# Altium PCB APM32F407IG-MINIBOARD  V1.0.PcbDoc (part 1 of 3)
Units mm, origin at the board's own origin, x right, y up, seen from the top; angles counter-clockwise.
Board outline 442.79 x 366.46 mm, 2 copper layers (Top Layer, Bottom Layer); 220 components, 190 nets, 1232 pads, 648 vias.
Unrouted connection lines stored in the file: 190.
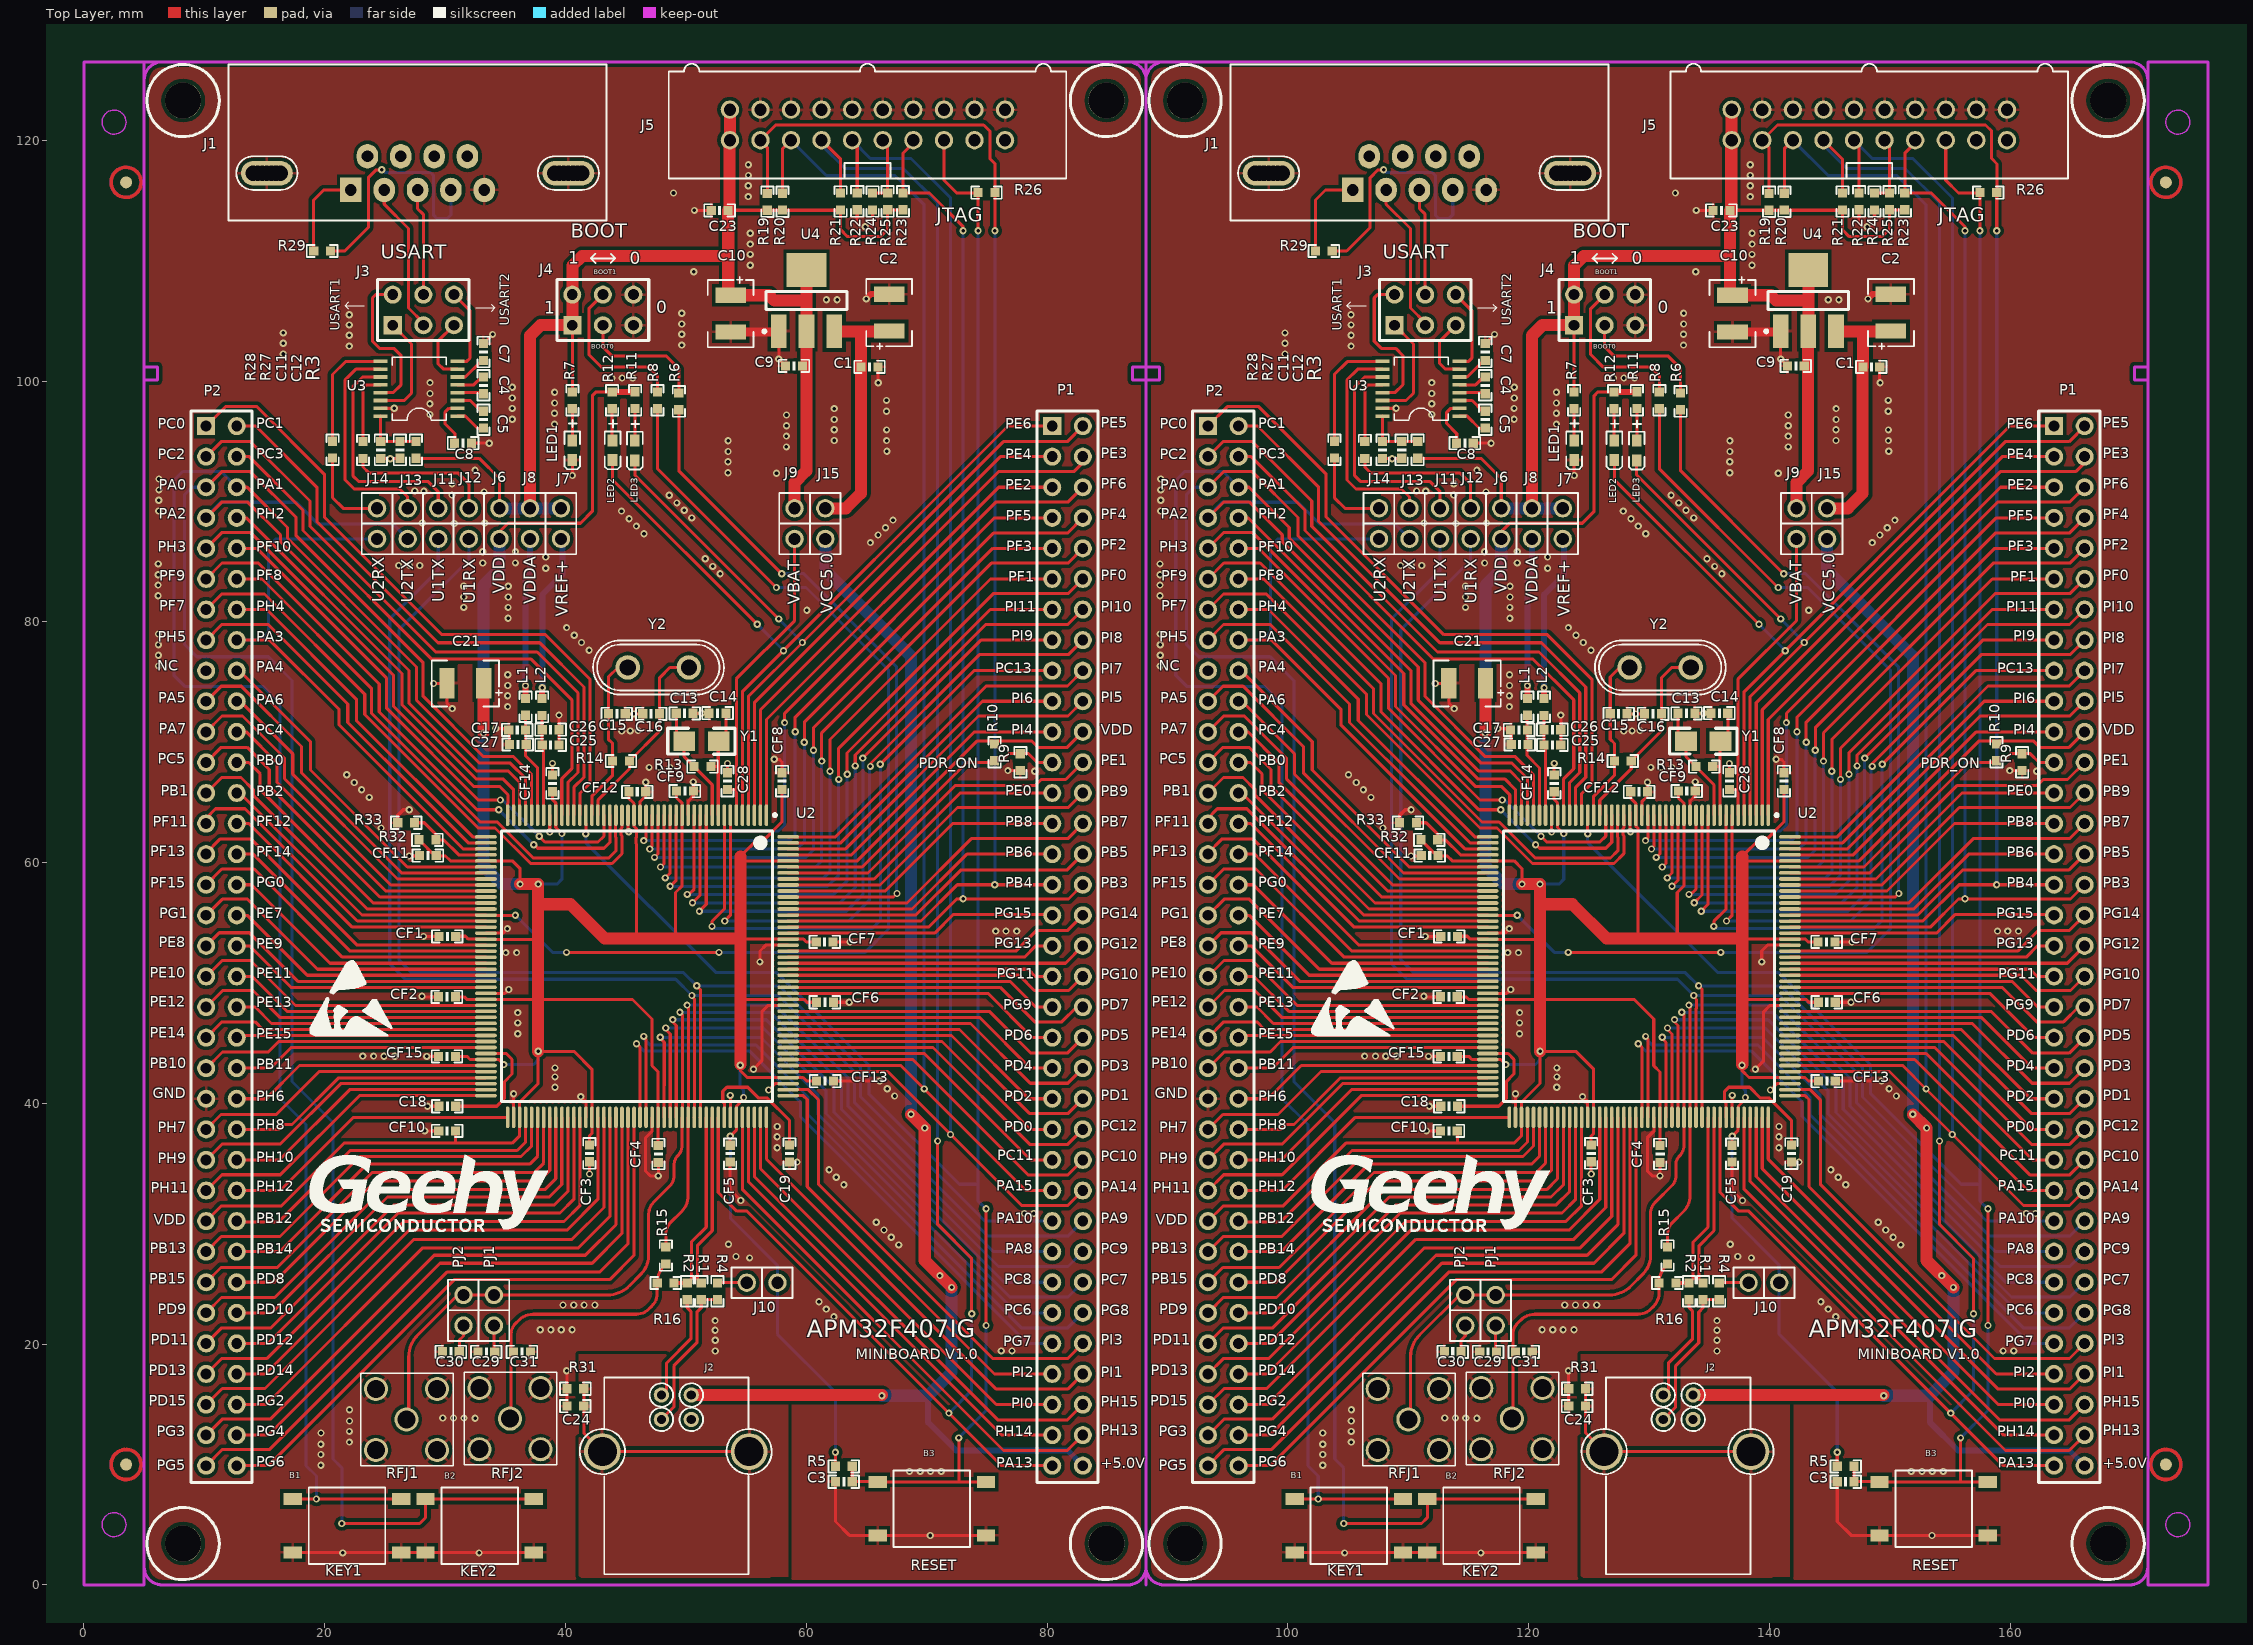
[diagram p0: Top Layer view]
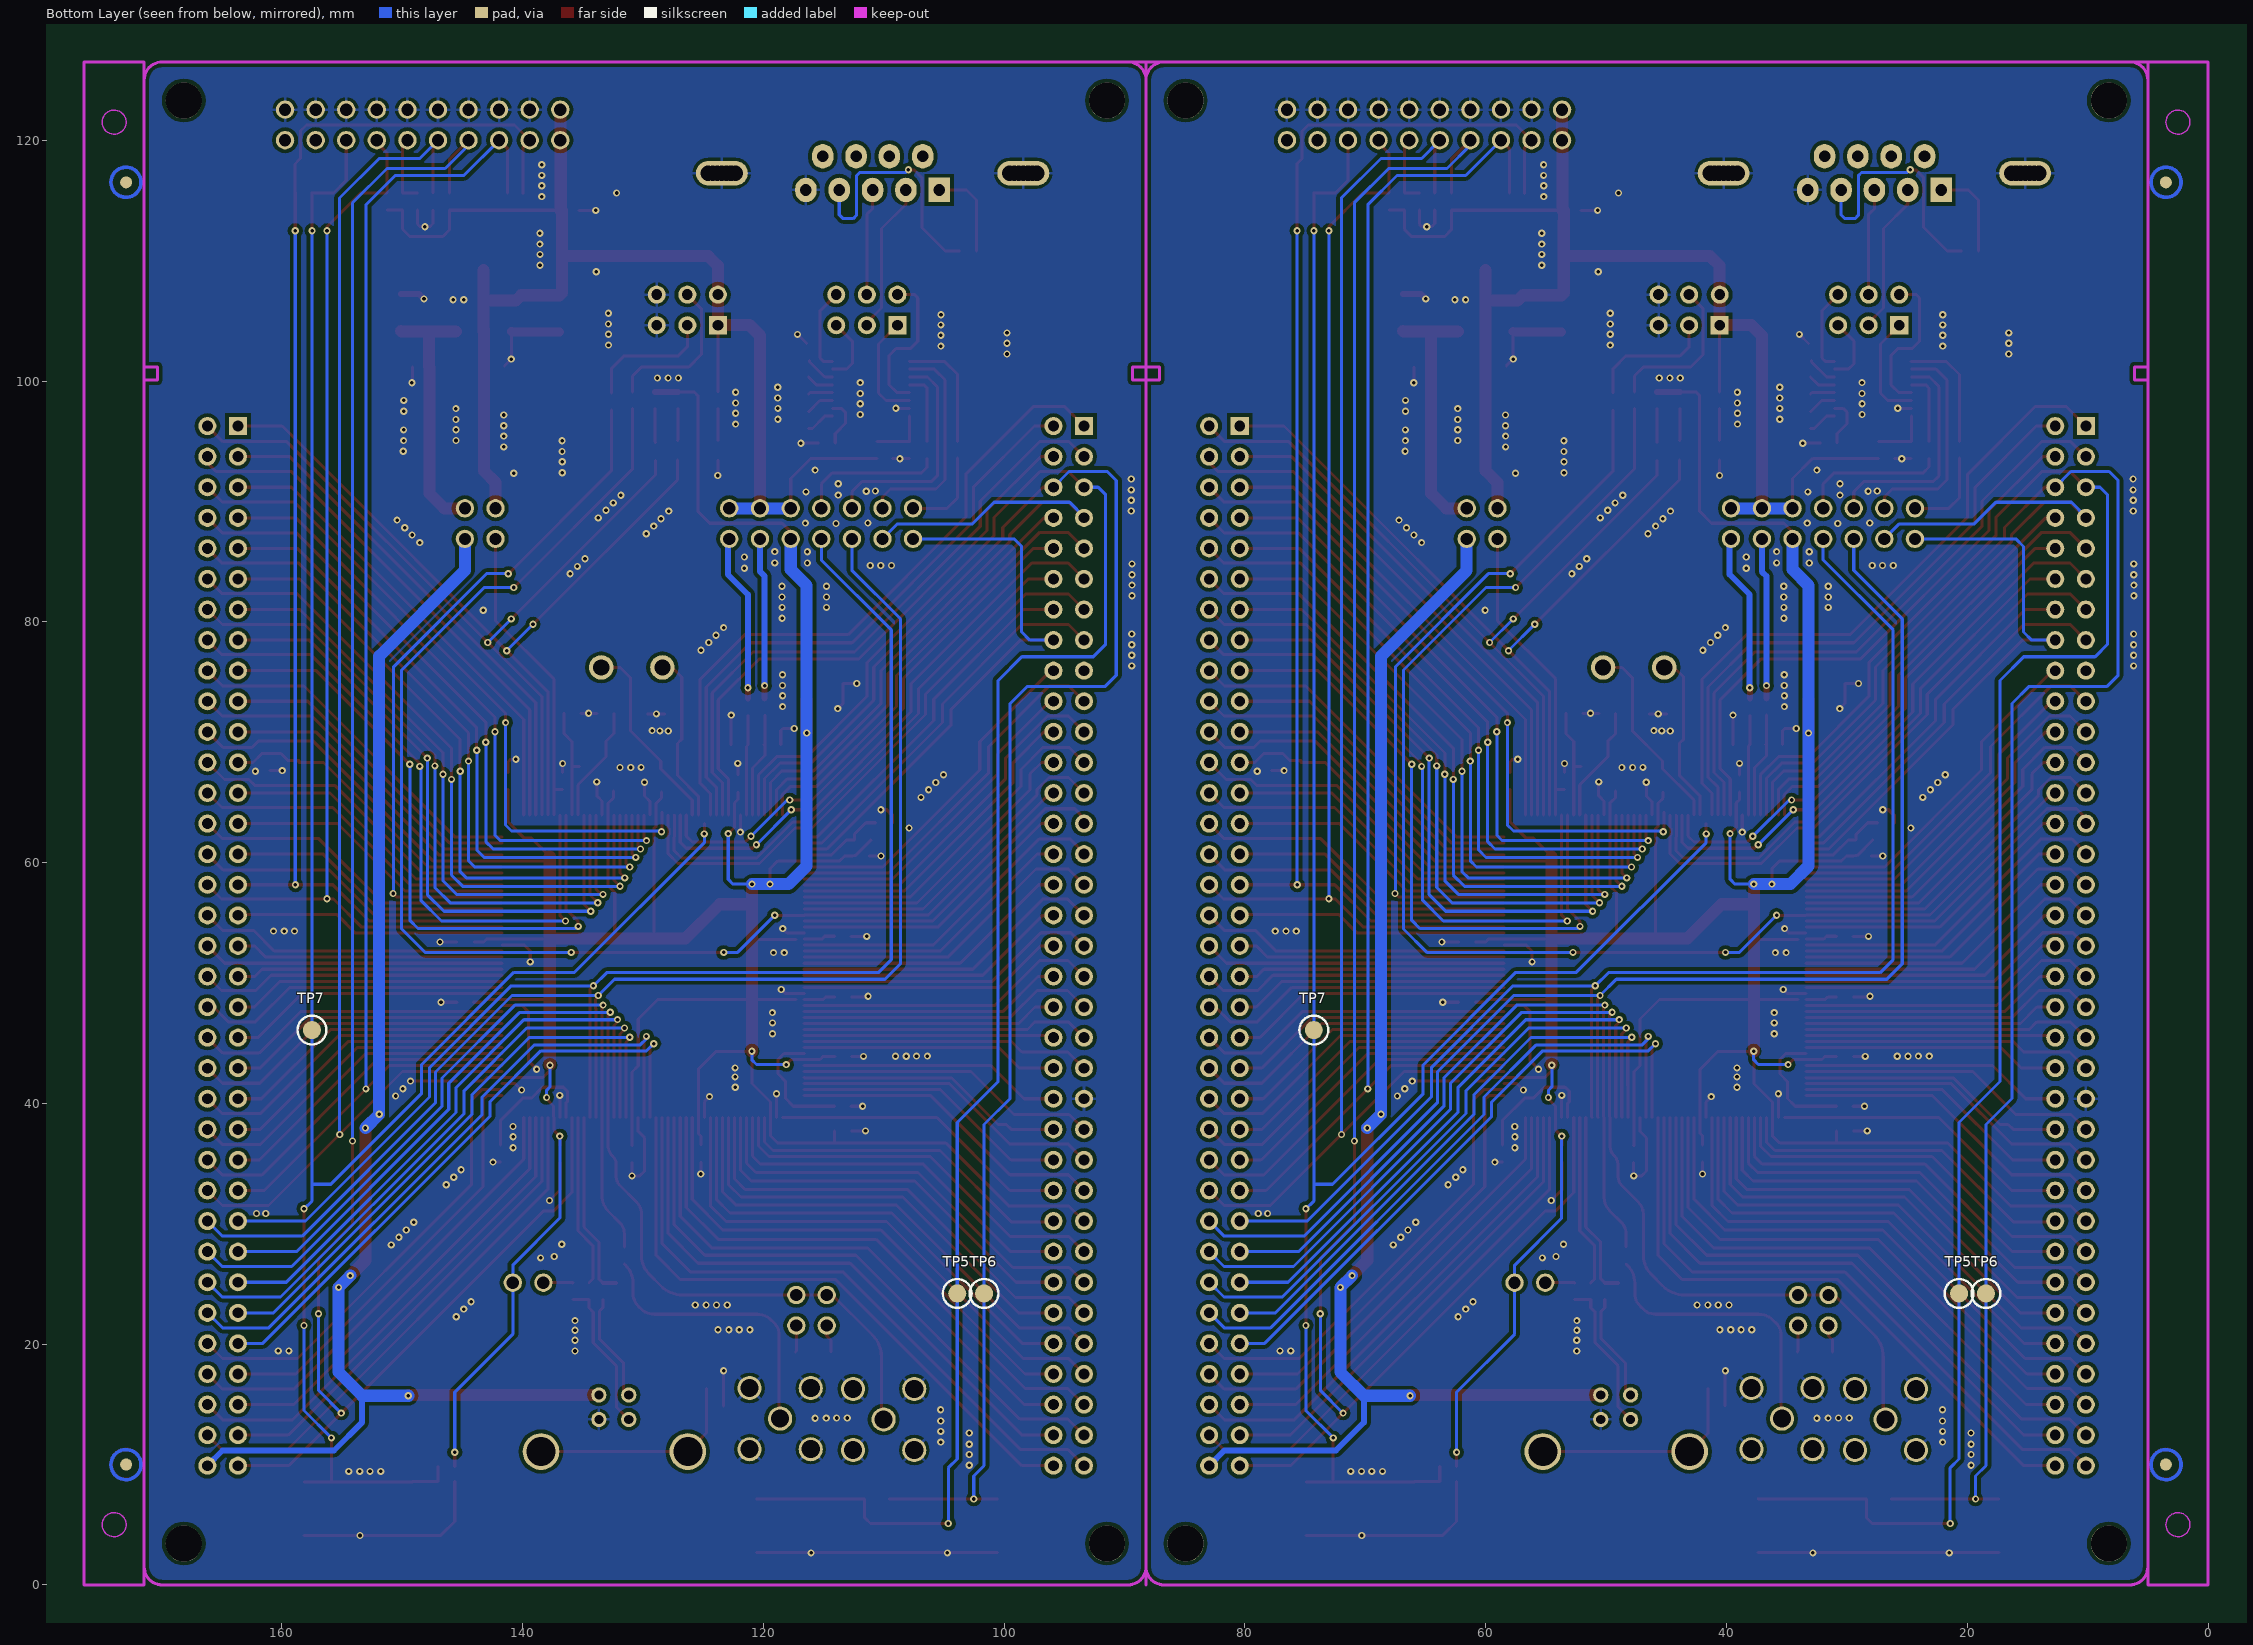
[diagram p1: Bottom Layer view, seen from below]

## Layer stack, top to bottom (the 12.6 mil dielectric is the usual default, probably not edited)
Top Layer: signal copper 0.0356
Dielectric: dielectric 0.32, FR-4, Dk 4.8
Bottom Layer: signal copper 0.0356

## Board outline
-115.13,-67.915 327.49,-67.915 327.49,298.005 327.12,298.375 326.95,298.545 -115.3,298.545

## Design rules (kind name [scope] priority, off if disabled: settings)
Clearance Clearance_1 [IsRegion] p1: gap=0.3
Clearance [All] p2: gap=0.2
ComponentClearance [All] p1: gap=0 collisioncheckmode=3 verticalgap=0 showdistances=FALSE
PolygonConnect [(InPadClass('All Pads'))] p1: connectstyle=Relief reliefconductorwidth=0.254 reliefentries=4 polygonreliefangle="90 Angle" airgapwidth=0.254
PolygonConnect PolygonConnect_1 [All] p2: connectstyle=Direct reliefconductorwidth=0.254 reliefentries=4 polygonreliefangle="90 Angle" airgapwidth=0.254
RoutingVias [All] p1: holewidth=0.3 width=0.6 viastyle="Through Hole" minholewidth=0.3 minwidth=0.6 maxholewidth=0.711 maxwidth=1.2
SilkToSolderMaskClearance SilkscreenOverComponentPads [IsPad] p1: minsilkscreentomaskgap=0.254 clearancetoexposedcopper=TRUE
SolderMaskExpansion [All] p1: expansion=0.102
Width Width_GND [InNet('GND')] p1: maxlimit=2 minlimit=0.3 preferedwidth=1
Width Width_C6-2 [InNet('NetC6_2')] p2: maxlimit=1.2 minlimit=1.2 preferedwidth=1.2
Width Width_MCU11 [InNet('MCU11')] p3: maxlimit=1.5 minlimit=0.3 preferedwidth=0.6
Width [All] p4: maxlimit=1 minlimit=0.15 preferedwidth=0.2 checkconnectedcopper=TRUE
26 further rules are at their usual default settings.

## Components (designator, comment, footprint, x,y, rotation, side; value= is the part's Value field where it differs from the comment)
B1 "Tamper" PB10 21.85,4.922 r90 top
B1 "Tamper" PB10 105.07,4.923 r90 top
B2 "Tamper" PB10 32.87,4.922 r90 top
B2 "Tamper" PB10 116.09,4.923 r90 top
B3 "Tamper" PB10 70.43,6.335 r90 top
B3 "Tamper" PB10 153.65,6.335 r90 top
C1 "100nF" 0603P 65.248,101.173 r180 top
C1 "100nF" 0603P 148.468,101.173 r180 top
C2 "3.3uF" TAN-B#1 66.88,105.69 r90 top
C2 "3.3uF" TAN-B#1 150.1,105.69 r90 top
C3 "100nF" 0603P 63.122,8.57 r0 top
C3 "100nF" 0603P 146.341,8.57 r0 top
C4 "100nF" 0603P 33.183,96.792 r90 top
C4 "100nF" 0603P 116.403,96.792 r90 top
C5 "100nF" 0603P 33.183,99.642 r90 top
C5 "100nF" 0603P 116.403,99.642 r90 top
C7 "100nF" 0603P 33.183,102.414 r270 top
C7 "100nF" 0603P 116.403,102.414 r270 top
C8 "100nF" 0603P 31.49,94.84 r180 top
C8 "100nF" 0603P 114.71,94.84 r180 top
C9 "100nF" 0603P 58.981,101.26 r0 top
C9 "100nF" 0603P 142.201,101.26 r0 top
C10 "3.3uF" TAN-B#1 53.72,105.604 r270 top
C10 "3.3uF" TAN-B#1 136.94,105.604 r270 top
C11 "100nF" 0603P 24.658,94.276 r270 top
C11 "100nF" 0603P 107.878,94.276 r270 top
C12 "100nF" 0603P 26.24,94.28 r90 top
C12 "100nF" 0603P 109.46,94.28 r90 top
C13 "10pF" 0603P 49.9,72.4 r180 top
C13 "10pF" 0603P 133.12,72.4 r180 top
C14 "10pF" 0603P 52.63,72.41 r0 top
C14 "10pF" 0603P 135.85,72.41 r0 top
C15 "20pF" 0603P 44.261,72.36 r180 top
C15 "20pF" 0603P 127.481,72.36 r180 top
C16 "20pF" 0603P 47.12,72.36 r0 top
C16 "20pF" 0603P 130.34,72.36 r0 top
C17 "10nF" 0603P 35.99,71.02 r0 top
C17 "10nF" 0603P 119.21,71.02 r0 top
C18 "2.2uF" 0603P 30.181,39.76 r0 top
C18 "2.2uF" 0603P 113.401,39.76 r0 top
C19 "2.2uF" 0603P 58.61,35.828 r270 top
C19 "2.2uF" 0603P 141.83,35.829 r270 top
C21 "47uF" TAN-B#2 31.676,74.88 r0 top
C21 "47uF" TAN-B#2 114.896,74.88 r0 top
C23 "100nF" 0603P 52.801,114.175 r0 top
C23 "100nF" 0603P 136.021,114.175 r0 top
C24 "4.7nF" 0603#1 40.113,14.855 r0 top
C24 "4.7nF" 0603#1 123.333,14.855 r0 top
C25 "1uF" 0603P 38.76,69.78 r180 top
C25 "1uF" 0603P 121.98,69.78 r180 top
C26 "10nF" 0603P 38.76,71.04 r180 top
C26 "10nF" 0603P 121.98,71.04 r180 top
C27 "1uF" 0603P 36.041,69.81 r0 top
C27 "1uF" 0603P 119.261,69.81 r0 top
C28 "100nF" 0603P 53.46,66.768 r270 top
C28 "100nF" 0603P 136.68,66.768 r270 top
C29 "30pF" 0603P 33.418,19.35 r180 top
C29 "30pF" 0603P 116.638,19.35 r180 top
C30 "40pF" 0603P 30.482,19.36 r180 top
C30 "40pF" 0603P 113.701,19.36 r180 top
C31 "10pF" 0603P 36.38,19.35 r0 top
C31 "10pF" 0603P 119.6,19.35 r0 top
CF1 "100nF" 0603P 30.182,53.87 r180 top
CF1 "100nF" 0603P 113.401,53.87 r180 top
CF2 "100nF" 0603P 30.152,48.85 r180 top
CF2 "100nF" 0603P 113.371,48.85 r180 top
CF3 "100nF" 0603P 41.98,35.841 r270 top
CF3 "100nF" 0603P 125.2,35.842 r270 top
CF4 "100nF" 0603P 47.71,35.791 r270 top
CF4 "100nF" 0603P 130.93,35.792 r270 top
CF5 "100nF" 0603P 53.68,35.82 r270 top
CF5 "100nF" 0603P 136.9,35.82 r270 top
CF6 "100nF" 0603P 61.551,48.4 r0 top
CF6 "100nF" 0603P 144.771,48.4 r0 top
CF7 "100nF" 0603P 61.532,53.41 r0 top
CF7 "100nF" 0603P 144.751,53.41 r0 top
CF8 "100nF" 0603P 57.99,66.77 r90 top
CF8 "100nF" 0603P 141.21,66.77 r90 top
CF9 "100nF" 0603P 49.92,65.94 r0 top
CF9 "100nF" 0603P 133.14,65.94 r0 top
CF10 "100nF" 0603P 30.163,37.71 r180 top
CF10 "100nF" 0603P 113.383,37.71 r180 top
CF11 "100nF" 0603P 28.568,60.58 r180 top
CF11 "100nF" 0603P 111.788,60.58 r180 top
CF12 "100nF" 0603P 45.96,65.88 r0 top
CF12 "100nF" 0603P 129.18,65.88 r0 top
CF13 "100nF" 0603P 61.56,41.85 r0 top
CF13 "100nF" 0603P 144.78,41.85 r0 top
CF14 "100nF" 0603P 38.91,66.578 r90 top
CF14 "100nF" 0603P 122.13,66.579 r90 top
CF15 "100nF" 0603P 30.152,43.9 r180 top
CF15 "100nF" 0603P 113.372,43.9 r180 top
J1 "DB9" DB9/F 22.176,115.875 r0 top
J1 "DB9" DB9/F 105.396,115.875 r0 top
J2 "USB-typeB connector" USB-B 50.451,15.774 r0 top
J2 "USB-typeB connector" USB-B 133.671,15.774 r0 top
J3 "Header 3X2" HDR2X3 25.651,104.637 r0 top
J3 "Header 3X2" HDR2X3 108.871,104.637 r0 top
J4 "Header 3X2" HDR2X3 40.563,104.637 r0 top
J4 "Header 3X2" HDR2X3 123.783,104.637 r0 top
J5 "JTAG" IDC20S 53.654,120.005 r90 top
J5 "JTAG" IDC20S 136.874,120.005 r90 top
J6 "" SIP2 34.51,89.43 r270 top
J6 "" SIP2 117.73,89.43 r270 top
J7 "" SIP2 39.62,89.43 r270 top
J7 "" SIP2 122.84,89.43 r270 top
J8 "" SIP2 37.06,89.43 r270 top
J8 "" SIP2 120.28,89.43 r270 top
J9 "" SIP2 59.03,89.43 r270 top
J9 "" SIP2 142.25,89.43 r270 top
J10 "" SIP2 57.6,25.105 r180 top
J10 "" SIP2 140.82,25.105 r180 top
J11 "" SIP2 29.43,89.43 r270 top
J11 "" SIP2 112.65,89.43 r270 top
J12 "" SIP2 31.97,89.43 r270 top
J12 "" SIP2 115.19,89.43 r270 top
J13 "" SIP2 26.89,89.43 r270 top
J13 "" SIP2 110.11,89.43 r270 top
J14 "" SIP2 24.35,89.43 r270 top
J14 "" SIP2 107.57,89.43 r270 top
J15 "" SIP2 61.58,89.43 r270 top
J15 "" SIP2 144.8,89.43 r270 top
L1 "0R" 0603#1 36.688,72.24 r90 top
L1 "0R" 0603#1 119.908,72.24 r90 top
L2 "0R" 0603#1 38.06,72.23 r90 top
L2 "0R" 0603#1 121.28,72.23 r90 top
LED1 "LED" D0603 40.563,93.436 r90 top
LED1 "LED" D0603 123.783,93.436 r90 top
LED2 "LED" D0603 43.907,93.424 r90 top
LED2 "LED" D0603 127.127,93.424 r90 top
LED3 "LED" D0603 45.76,93.406 r90 top
LED3 "LED" D0603 128.98,93.406 r90 top
P1 "Header 35X2" HDR2X35 80.431,96.261 r270 top
P1 "Header 35X2" HDR2X35 163.651,96.261 r270 top
P2 "Header 35X2" HDR2X35 10.15,96.261 r270 top
P2 "Header 35X2" HDR2X35 93.37,96.261 r270 top
PJ1 "" SIP2 34.05,21.54 r90 top
PJ1 "" SIP2 117.27,21.54 r90 top
PJ2 "" SIP2 31.52,21.54 r90 top
PJ2 "" SIP2 114.74,21.54 r90 top
R1 "22R" 0603#2 51.273,24.387 r90 top
R1 "22R" 0603#2 134.493,24.387 r90 top
R2 "22R" 0603#2 50.114,24.387 r90 top
R2 "22R" 0603#2 133.334,24.387 r90 top
R3 "0R" 0603#1 27.57,94.98 r270 top
R3 "0R" 0603#1 110.79,94.98 r270 top
R4 "1.5K" 0603#2 52.614,24.387 r90 top
R4 "1.5K" 0603#2 135.834,24.387 r90 top
R5 "10K" 0603#2 63.122,9.85 r0 top
R5 "10K" 0603#2 146.341,9.85 r0 top
R6 "10K" 0603#2 49.41,98.308 r90 top
R6 "10K" 0603#2 132.63,98.308 r90 top
R7 "470R" 0603#2 40.563,98.397 r90 top
R7 "470R" 0603#2 123.783,98.397 r90 top
R8 "10K" 0603#2 47.64,98.397 r270 top
R8 "10K" 0603#2 130.86,98.397 r270 top
R9 "10K" 0603#1 77.78,67.64 r90 top
R9 "10K" 0603#1 161,67.64 r90 top
R10 "10K" 0603#1 75.64,68.463 r90 top
R10 "10K" 0603#1 158.86,68.463 r90 top
R11 "470R" 0603#2 45.78,98.411 r270 top
R11 "470R" 0603#2 129,98.411 r270 top
R12 "470R" 0603#2 43.877,98.401 r270 top
R12 "470R" 0603#2 127.097,98.401 r270 top
R13 "NC" 0603#2 51.38,67.97 r180 top
R13 "NC" 0603#2 134.6,67.97 r180 top
R14 "NC" 0603#2 44.612,68.44 r180 top
R14 "NC" 0603#2 127.831,68.44 r180 top
R15 "0R" 0603#1 48.333,28.057 r270 top
R15 "0R" 0603#1 131.552,28.057 r270 top
R16 "0R" 0603#1 47.618,25.075 r0 top
R16 "0R" 0603#1 130.838,25.075 r0 top
R19 "10K" 0603#2 56.764,114.885 r270 top
R19 "10K" 0603#2 139.984,114.885 r270 top
R20 "10K" 0603#2 58.024,114.905 r270 top
R20 "10K" 0603#2 141.244,114.905 r270 top
R21 "10K" 0603#2 62.854,114.915 r270 top
R21 "10K" 0603#2 146.074,114.915 r270 top
R22 "10K" 0603#2 64.234,114.925 r90 top
R22 "10K" 0603#2 147.454,114.925 r90 top
R23 "10K" 0603#2 68.034,114.925 r270 top
R23 "10K" 0603#2 151.254,114.925 r270 top
R24 "10K" 0603#2 65.514,114.915 r90 top
R24 "10K" 0603#2 148.734,114.915 r90 top
R25 "10K" 0603#2 66.764,114.925 r270 top
R25 "10K" 0603#2 149.984,114.925 r270 top
R26 "10K" 0603#2 74.97,115.655 r0 top
R26 "10K" 0603#2 158.19,115.655 r0 top
R27 "0R" 0603#2 23.174,94.275 r90 top
R27 "0R" 0603#2 106.394,94.275 r90 top
R28 "0R" 0603#2 20.65,94.3 r90 top
R28 "0R" 0603#2 103.87,94.3 r90 top
R29 "0R" 0603#2 19.78,110.805 r180 top
R29 "0R" 0603#2 103,110.805 r180 top
R31 "1M" 0603#2 40.822,16.295 r0 top
R31 "1M" 0603#2 124.041,16.295 r0 top
R32 "DIN" 0603#1 29.23,61.89 r180 top (schematic designator R10)
R32 "DIN" 0603#1 112.45,61.89 r180 top (schematic designator R10)
R33 "10K" 0603#1 26.063,63.31 r0 top (schematic designator R9)
R33 "10K" 0603#1 109.283,63.31 r0 top (schematic designator R9)
RFJ1 "SMA" "RFCON - SMA" 26.79,13.74 r0 top
RFJ1 "SMA" "RFCON - SMA" 110.01,13.74 r0 top
RFJ2 "SMA" "RFCON - SMA" 35.39,13.81 r0 top
RFJ2 "SMA" "RFCON - SMA" 118.61,13.81 r0 top
TP5 "" TP1.5 20.68,24.21 r180 bottom
TP5 "" TP1.5 103.9,24.21 r180 bottom
TP6 "" TP1.5 18.45,24.21 r180 bottom
TP6 "" TP1.5 101.67,24.21 r180 bottom
TP7 "" TP1.5 74.282,46.09 r180 bottom
TP7 "" TP1.5 157.502,46.09 r180 bottom
U2 "STM32F407IGT6" LQFP-176N 45.94,51.39 r270 top
U2 "STM32F407IGT6" LQFP-176N 129.16,51.39 r270 top
U3 "ST3232ECTR" TSSOP16 31.035,97.084 r180 top
U3 "ST3232ECTR" TSSOP16 114.255,97.084 r180 top
U4 "AMS1117" SPX1117M 60.02,106.68 r90 top
U4 "AMS1117" SPX1117M 143.24,106.68 r90 top
Y1 "32.768KHz" R1206 49.851,70.08 r0 top
Y1 "32.768KHz" R1206 133.071,70.08 r0 top
Y2 "8MHz" XTAL_socket 47.71,76.21 r180 top
Y2 "8MHz" XTAL_socket 130.93,76.21 r180 top

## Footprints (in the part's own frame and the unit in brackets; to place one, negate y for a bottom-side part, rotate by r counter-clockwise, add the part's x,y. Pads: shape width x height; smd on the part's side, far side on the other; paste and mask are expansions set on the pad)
0603#1 [mil]
  rect 30x30 smd: 1(0,0) 2(55,0)
  silkscreen extent -23,-20 77,20
0603#2 [mil]
  rect 30x30 smd: 1(-27.5,0) 2(27.5,0)
  silkscreen extent -50,-20 50,20
0603P [mil]
  rect 30x30 smd: 1(-27.5,0) 2(27.5,0)
  silkscreen extent -50,-20 50,20
D0603 [mm]
  rect 1x0.8 smd: 1(1.637,0) 2(0,0)
  silkscreen extent -0.76,-0.65 3.34,0.65
DB9/F [mil]
  round 50 hole 50: 0(-320,55) 0(-305,55) 0(-290,55) 0(-275,55) 0(-260,55) 0(-245,55) 0(-230,55) 0(666,55) 0(681,55) 0(696,55) 0(711,55) 0(726,55) 0(741,55) 0(756,55)
  oval 170x80 hole 50: 0(-275,55) 0(711,55)
  rect 70x80 hole 38: 1(0,0)
  oval 70x80 hole 38: 2(109,0) 3(218,0) 4(327,0) 5(436,0) 6(54,110) 7(163,110) 8(272,110) 9(381,110)
  silkscreen extent -400,-100 836,410
HDR2X3 [mm] "Connector; Header; 3x2 Position"
  rect 1.5x1.5 hole 0.9: 1(0,0)
  round 1.5 hole 0.9: 2(0,2.54) 3(2.54,0) 4(2.54,2.54) 5(5.08,0) 6(5.08,2.54)
  silkscreen extent -1.27,-1.27 6.35,3.81
HDR2X35 [mm] "Connector; Header; 30x2 Position"
  rect 1.5x1.5 hole 0.9: 1(0,0)
  round 1.5 hole 0.9: 2(0,2.54) 3(2.54,0) 4(2.54,2.54) 5(5.08,0) 6(5.08,2.54) 7(7.62,0) 8(7.62,2.54) 9(10.16,0) 10(10.16,2.54) 11(12.7,0) 12(12.7,2.54) 13(15.24,0) 14(15.24,2.54) 15(17.78,0) 16(17.78,2.54) 17(20.32,0) 18(20.32,2.54) 19(22.86,0) 20(22.86,2.54) 21(25.4,0) 22(25.4,2.54) 23(27.94,0) 24(27.94,2.54) 25(30.48,0) 26(30.48,2.54) 27(33.02,0) 28(33.02,2.54) 29(35.56,0) 30(35.56,2.54) 31(38.1,0) 32(38.1,2.54) 33(40.64,0) 34(40.64,2.54) 35(43.18,0) 36(43.18,2.54) 37(45.72,0) 38(45.72,2.54) 39(48.26,0) 40(48.26,2.54) 41(50.8,0) 42(50.8,2.54) 43(53.34,0) 44(53.34,2.54) 45(55.88,0) 46(55.88,2.54) 47(58.42,0) 48(58.42,2.54) 49(60.96,0) 50(60.96,2.54) 51(63.5,0) 52(63.5,2.54) 53(66.04,0) 54(66.04,2.54) 55(68.58,0) 56(68.58,2.54) 57(71.12,0) 58(71.12,2.54) 59(73.66,0) 60(73.66,2.54) 61(76.2,0) 62(76.2,2.54) 63(78.74,0) 64(78.74,2.54) 65(81.28,0) 66(81.28,2.54) 67(83.82,0) 68(83.82,2.54) 69(86.36,0) 70(86.36,2.54)
  silkscreen extent -1.27,-1.27 87.76,3.81
IDC20S [mil]
  round 60 hole 40: 1(0,0) 2(100,0) 3(0,-100) 4(100,-100) 5(0,-200) 6(100,-200) 7(0,-300) 8(100,-300) 9(0,-400) 10(100,-400) 11(0,-500) 12(100,-500) 13(0,-600) 14(100,-600) 15(0,-700) 16(100,-700) 17(0,-800) 18(100,-800) 19(0,-900) 20(100,-900)
  silkscreen extent -125,-1100 250,200
LQFP-176N [mm] "Thin QFP, 176-Leads, Body 24x24mm, Pitch 0.5mm, IPC Medium Density"
  oval 1.8x0.3 smd: 1(-12.55,10.75) 2(-12.55,10.25) 3(-12.55,9.75) 4(-12.55,9.25) 5(-12.55,8.75) 6(-12.55,8.25) 7(-12.55,7.75) 8(-12.55,7.25) 9(-12.55,6.75) 10(-12.55,6.25) 11(-12.55,5.75) 12(-12.55,5.25) 13(-12.55,4.75) 14(-12.55,4.25) 15(-12.55,3.75) 16(-12.55,3.25) 17(-12.55,2.75) 18(-12.55,2.25) 19(-12.55,1.75) 20(-12.55,1.25) 21(-12.55,0.75) 22(-12.55,0.25) 23(-12.55,-0.25) 24(-12.55,-0.75) 25(-12.55,-1.25) 26(-12.55,-1.75) 27(-12.55,-2.25) 28(-12.55,-2.75) 29(-12.55,-3.25) 30(-12.55,-3.75) 31(-12.55,-4.25) 32(-12.55,-4.75) 33(-12.55,-5.25) 34(-12.55,-5.75) 35(-12.55,-6.25) 36(-12.55,-6.75) 37(-12.55,-7.25) 38(-12.55,-7.75) 39(-12.55,-8.25) 40(-12.55,-8.75) 41(-12.55,-9.25) 42(-12.55,-9.75) 43(-12.55,-10.25) 44(-12.55,-10.75) 89(12.55,-10.75) 90(12.55,-10.25) 91(12.55,-9.75) 92(12.55,-9.25) 93(12.55,-8.75) 94(12.55,-8.25) 95(12.55,-7.75) 96(12.55,-7.25) 97(12.55,-6.75) 98(12.55,-6.25) 99(12.55,-5.75) 100(12.55,-5.25) 101(12.55,-4.75) 102(12.55,-4.25) 103(12.55,-3.75) 104(12.55,-3.25) 105(12.55,-2.75) 106(12.55,-2.25) 107(12.55,-1.75) 108(12.55,-1.25) 109(12.55,-0.75) 110(12.55,-0.25) 111(12.55,0.25) 112(12.55,0.75) 113(12.55,1.25) 114(12.55,1.75) 115(12.55,2.25) 116(12.55,2.75) 117(12.55,3.25) 118(12.55,3.75) 119(12.55,4.25) 120(12.55,4.75) 121(12.55,5.25) 122(12.55,5.75) 123(12.55,6.25) 124(12.55,6.75) 125(12.55,7.25) 126(12.55,7.75) 127(12.55,8.25) 128(12.55,8.75) 129(12.55,9.25) 130(12.55,9.75) 131(12.55,10.25) 132(12.55,10.75)
  oval 0.3x1.8 smd: 45(-10.75,-12.55) 46(-10.25,-12.55) 47(-9.75,-12.55) 48(-9.25,-12.55) 49(-8.75,-12.55) 50(-8.25,-12.55) 51(-7.75,-12.55) 52(-7.25,-12.55) 53(-6.75,-12.55) 54(-6.25,-12.55) 55(-5.75,-12.55) 56(-5.25,-12.55) 57(-4.75,-12.55) 58(-4.25,-12.55) 59(-3.75,-12.55) 60(-3.25,-12.55) 61(-2.75,-12.55) 62(-2.25,-12.55) 63(-1.75,-12.55) 64(-1.25,-12.55) 65(-0.75,-12.55) 66(-0.25,-12.55) 67(0.25,-12.55) 68(0.75,-12.55) 69(1.25,-12.55) 70(1.75,-12.55) 71(2.25,-12.55) 72(2.75,-12.55) 73(3.25,-12.55) 74(3.75,-12.55) 75(4.25,-12.55) 76(4.75,-12.55) 77(5.25,-12.55) 78(5.75,-12.55) 79(6.25,-12.55) 80(6.75,-12.55) 81(7.25,-12.55) 82(7.75,-12.55) 83(8.25,-12.55) 84(8.75,-12.55) 85(9.25,-12.55) 86(9.75,-12.55) 87(10.25,-12.55) 88(10.75,-12.55) 133(10.75,12.55) 134(10.25,12.55) 135(9.75,12.55) 136(9.25,12.55) 137(8.75,12.55) 138(8.25,12.55) 139(7.75,12.55) 140(7.25,12.55) 141(6.75,12.55) 142(6.25,12.55) 143(5.75,12.55) 144(5.25,12.55) 145(4.75,12.55) 146(4.25,12.55) 147(3.75,12.55) 148(3.25,12.55) 149(2.75,12.55) 150(2.25,12.55) 151(1.75,12.55) 152(1.25,12.55) 153(0.75,12.55) 154(0.25,12.55) 155(-0.25,12.55) 156(-0.75,12.55) 157(-1.25,12.55) 158(-1.75,12.55) 159(-2.25,12.55) 160(-2.75,12.55) 161(-3.25,12.55) 162(-3.75,12.55) 163(-4.25,12.55) 164(-4.75,12.55) 165(-5.25,12.55) 166(-5.75,12.55) 167(-6.25,12.55) 168(-6.75,12.55) 169(-7.25,12.55) 170(-7.75,12.55) 171(-8.25,12.55) 172(-8.75,12.55) 173(-9.25,12.55) 174(-9.75,12.55) 175(-10.25,12.55) 176(-10.75,12.55)
  silkscreen extent -12.67,-11.25 11.25,11.58, body extent -12,-12 12,12, height 1.6
PB10 [mil]
  rect 40x60 smd: 1(-87.5,177.17) 2(87.5,177.17) 3(87.5,-177.17) 4(-87.5,-177.17)
  silkscreen extent -125,-125 125,125
R1206 [mm]
  rect 1.8x1.6 smd: 1(0,0) 2(2.865,0)
  silkscreen extent -1.36,-1.08 4.24,1.08
"RFCON - SMA" [mm]
  round 2 hole 1.5: 1(-2.54,-2.54) 2(2.54,-2.54) 3(2.54,2.54) 4(-2.54,2.54) 5(0,0)
  silkscreen extent -3.8,-3.85 3.9,3.84
SIP2 [mil]
  round 60 hole 40: 1(0,0) 2(100,0)
  silkscreen extent -50,-50 150,50
SPX1117M [mm]
  rect 2.8x1.3 smd: 1(-2.55,2.3) 2(-2.55,0) 3(-2.55,-2.3)
  rect 2.8x3.3 smd: 4(2.55,0)
  silkscreen extent -2.67,-3.35 0.75,3.62
TAN-B#1 [mil]
  rect 50x100 smd: 1(-60,0) 2(60,0)
  silkscreen extent -120,-75 110,75
TAN-B#2 [mil]
  rect 50x100 smd: 1(60,0) 2(-60,0)
  silkscreen extent -110,-75 120,75
TP1.5 [mm]
  round 1.5 smd: 1(0,0)
  silkscreen extent -1.2,-1.2 1.2,1.2
TSSOP16 [mm]
  rect 1.15x0.3 smd: 1(0,0) 2(0,-0.65) 3(0,-1.3) 4(0,-1.95) 5(0,-2.6) 6(0,-3.25) 7(0,-3.9) 8(0,-4.55) 9(6.4,-4.55) 10(6.4,-3.9) 11(6.4,-3.25) 12(6.4,-2.6) 13(6.4,-1.95) 14(6.4,-1.3) 15(6.4,-0.65) 16(6.4,0)
  silkscreen extent 0.94,-4.88 5.42,0.33
USB-B [mil]
  round 120 hole 95: 0(-291,-185) 0(189,-185)
  round 50 hole 30: 1(0,0) 2(-98,0) 3(-98,-80) 4(0,-80)
  silkscreen extent -365,-586 263,57
XTAL_socket [mil]
  round 80 hole 53: 1(100,0) 2(-100,0)
  silkscreen extent -215,-89 214,89

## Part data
B1 B1 B2 B2 B3 B3: library part "SW PUSHBUTTON", "SE PUSHBUTTON"
C1 C1 C3 C3 C9 C9 C12 C12 C13 C13 C14 C14 C15 C15 C16 C16 C17 C17 C18 C18 C19 C19 C23 C23 C25 C25 C26 C26 C27 C27 C28 C28 C29 C29 C30 C30 C31 C31: library part Cap, "Capacitor"
C2 C2 C10 C10: library part Cap2, "Capacitor"
C4 C4 C5 C5 C7 C7 C8 C8 C11 C11 C24 C24 CF1 CF1 CF2 CF2 CF3 CF3 CF4 CF4 CF5 CF5 CF6 CF6 CF7 CF7 CF8 CF8 CF9 CF9 CF10 CF10 CF11 CF11 CF12 CF12 CF13 CF13 CF14 CF14 CF15 CF15: library part CAP, "Capacitor"
C21 C21: library part "Cap Pol1", "Polarized Capacitor (Radial)"
J2 J2: library part USB-B, "USB-B"
J3 J3 J4 J4: "Header, 3-Pin, Dual row"
J5 J5: library part "Header 10X2", "Header, 10-Pin, Dual row"
J6 J6 J7 J7 J8 J8 J9 J9 J10 J10 J11 J11 J12 J12 J13 J13 J14 J14 J15 J15 PJ1 PJ1 PJ2 PJ2: library part JP2
L1 L1 L2 L2: library part Inductor, "Inductor"
LED1 LED1 LED2 LED2 LED3 LED3: library part LED2, "Typical RED, GREEN, YELLOW, AMBER GaAs LED"
P1 P1 P2 P2: "Header, 30-Pin, Dual row"
R1 R1 R2 R2 R3 R3 R4 R4 R5 R5 R6 R6 R7 R7 R8 R8 R11 R11 R12 R12 R13 R13 R14 R14 R15 R15 R16 R16 R19 R19 R20 R20 R21 R21 R22 R22 R23 R23 R24 R24 R25 R25 R26 R26 R27 R27 R28 R28 R29 R29: library part Res2, "Resistor"
R9 R9 R10 R10 R31 R31 R32 R32 R33 R33: library part RES, "'1/8W 5%"
RFJ1 RFJ1 RFJ2 RFJ2: library part "Header 5", "Header, 5-Pin"
TP5 TP5 TP6 TP6 TP7 TP7: library part TP
U3 U3: library part ST3232, "3.3V/5V Dual RS232 Transceiver w/ Int. Cap."
U4 U4: library part SPX1117
Y1 Y1: library part XTAL, "Crystal Oscillator"
Y2 Y2: library part CRYSTAL, "Crystal"

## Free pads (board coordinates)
  round 3 hole 3 paste+0 mask+0: 0(8.24,123.3) 0(8.24,3.43) 0(84.93,123.3) 0(84.93,3.43) 0(91.46,123.3) 0(91.46,3.43) 0(168.15,123.3) 0(168.15,3.43)
  round 1 smd: 1(3.5,10) 1(3.5,116.505) 1(172.94,10) 1(172.94,116.505)
  round 1 smd far side: 6(3.5,10) 6(3.5,116.505) 6(172.94,10) 6(172.94,116.505)

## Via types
v1: diameter 0.6, hole 0.3, Top Layer to Bottom Layer, 648 vias

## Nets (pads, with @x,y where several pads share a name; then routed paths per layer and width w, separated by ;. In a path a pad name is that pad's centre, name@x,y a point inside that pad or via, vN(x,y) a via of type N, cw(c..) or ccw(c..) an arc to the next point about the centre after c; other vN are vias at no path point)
+3.3V: C9.2 C10.1 C23.2 J4.1 J4.2 J5.1 J5.2 J6.1 J7.1 J8.1 J9.1 R3.2 R7.2 R19.2 R20.2 R21.2 R23.2 R25.2 U4.2 U4.4 | length 242
  Top Layer w0.254: R3.2@27.36,93.58 R3.2@27.57,93.58 ; R3.2@27.57,93.583 32.832,93.583 34.51,91.905 J6.1@34.51,89.43 ; R7.2@40.563,99.095 40.563,104.617 J4.1@40.563,104.637 ; C23.2@53.5,114.175 53.511,114.186 53.614,114.186 R19.2@56.764,114.186 62.824,114.186 R21.2@62.854,114.216 62.854,112.565 63.424,111.995 66.144,111.995 66.764,112.615 R25.2@66.764,114.226 ; R25.2@66.764,114.226 R23.2@68.034,114.226 ; R3.2@110.58,93.58 R3.2@110.79,93.58 ; R3.2@110.79,93.583 116.052,93.583 117.73,91.905 J6.1@117.73,89.43 ; R7.2@123.783,99.095 123.783,104.617 J4.1@123.783,104.637 ; C23.2@136.72,114.175 136.731,114.186 136.834,114.186 R19.2@139.984,114.186 146.044,114.186 R21.2@146.074,114.216 146.074,112.565 146.644,111.995 149.364,111.995 149.984,112.615 R25.2@149.984,114.226 R23.2@151.254,114.226
  Top Layer w1: J8.1@37.06,89.43 37.06,103.78 37.93,104.65 40.53,104.65 40.563,104.617 40.57,104.61 40.57,109.585 41.364,110.379 53.481,110.379 ; 53.5,110.36 C23.2@53.5,114.175 ; 53.501,113.319 53.52,113.3 53.52,107.328 C10.1@53.72,107.128 56.902,107.128 57.35,106.68 60.02,106.68 ; C23.2@53.614,114.186 J5.1@53.614,119.964 ; J5.1@53.654,120.005 J5.2@53.654,122.545 ; J9.1@59.03,89.43 59.03,91.57 60,92.54 60,104.13 U4.2@60,104.31 ; U4.2@60.02,104.13 60.02,106.68 ; U4.4@60.02,109.23 60.02,106.68 ; J8.1@120.28,89.43 120.28,103.78 121.15,104.65 123.75,104.65 123.783,104.617 123.79,104.61 123.79,109.585 124.584,110.379 136.701,110.379 ; 136.72,110.36 C23.2@136.72,114.175 ; 136.721,113.319 136.74,113.3 136.74,107.328 C10.1@136.94,107.128 140.122,107.128 140.57,106.68 143.24,106.68 ; C23.2@136.834,114.186 J5.1@136.834,119.964 ; J5.1@136.874,120.005 J5.2@136.874,122.545 ; J9.1@142.25,89.43 142.25,91.57 143.22,92.54 143.22,104.13 U4.2@143.22,104.31 ; U4.2@143.24,104.13 143.24,106.68 ; U4.4@143.24,109.23 143.24,106.68
  Bottom Layer w1: J6.1@34.51,89.43 J8.1@37.06,89.43 J7.1@39.62,89.43 ; J6.1@117.73,89.43 J8.1@120.28,89.43 J7.1@122.84,89.43
+5.0V: J2.1 J15.2 P1.70 | length 231.1
  Top Layer w1: J2.1@50.451,15.774 v1@66.28,15.774 ; v1(68.7,39.09) v1(69.84,37.95) 69.84,26.94 v1(72.07,24.71) ; J2.1@133.671,15.774 v1@149.5,15.774 ; v1(151.92,39.09) v1(153.06,37.95) 153.06,26.94 v1(155.29,24.71)
  Bottom Layer w0.5: 70.11,15.71 70.11,13.5 72.45,11.16 81.711,11.16 P1.70@82.971,9.901 ; 153.33,15.71 153.33,13.5 155.67,11.16 164.931,11.16 P1.70@166.191,9.901
  Bottom Layer w1: J15.2@61.58,86.89 61.58,84.26 68.7,77.14 v1(68.7,39.09) v1(69.84,37.95) ; v1(66.28,15.71) 70.11,15.71 72.07,17.67 v1(72.07,24.71) 72.07,24.72 v1(71.1,25.69) v1@71.09,25.7 ; J15.2@144.8,86.89 144.8,84.26 151.92,77.14 v1(151.92,39.09) v1(153.06,37.95) ; v1(149.5,15.71) 153.33,15.71 155.29,17.67 v1(155.29,24.71) 155.29,24.72 v1(154.32,25.69) v1@154.31,25.7
BYPASS_RGE: R32.1 R33.2 U2.48 | length 14.6
  Top Layer w0.254: R33.2@27.46,63.31 28.27,63.31 29.23,62.35 R32.1@29.23,61.89 29.87,61.89 31.12,60.64 U2.48@33.39,60.64 ; R33.2@110.68,63.31 111.49,63.31 112.45,62.35 R32.1@112.45,61.89 113.09,61.89 114.34,60.64 U2.48@116.61,60.64
GND: B1.1 B1.4 B2.1 B2.4 B3.1 B3.4 C1.1 C2.2 C3.1 C7.1 C8.1 C9.1 C10.2 C11.2 C12.1 C13.1 C14.1 C15.1 C16.1 C17.1 C18.1 C19.2 C21.2 C23.1 C24.1 C25.1 C26.1 C27.1 C28.1 C29.2 C30.2 C31.2 CF1.2 CF2.2 CF3.2 CF4.2 CF5.2 CF6.2 CF7.2 CF8.2 CF9.2 CF10.2 CF11.2 CF12.2 CF13.2 CF14.2 CF15.2 J1.0 J1.5 J2.4 J4.5 J4.6 J5.4 J5.6 J5.8 J5.10 J5.12 J5.14 J5.16 J5.18 J5.20 LED1.2 P2.45 R9.1 R22.1 R24.1 R31.1 R33.1 RFJ1.1 RFJ1.2 RFJ1.3 RFJ1.4 RFJ2.1 RFJ2.2 RFJ2.3 RFJ2.4 U2.14 U2.22 U2.37 U2.61 U2.71 U2.90 U2.102 U2.113 U2.126 U2.135 U2.148 U2.158 U3.15 U4.1 | length 267.8
  Top Layer w0.254: B1.1@17.35,2.7 B2.1@28.37,2.7 B2.4@37.37,2.7 ; U3.15@24.635,97.734 v1(25.774,97.735) ; C11.2@24.658,93.578 25.44,93.578 C12.1@26.048,93.578 ; v1(27.016,60.55) CF11.2@27.993,60.55 ; v1(28.082,48.89) 28.082,48.87 28.072,48.86 28.082,48.85 CF2.2@29.453,48.85 ; v1(28.202,53.87) 28.183,53.852 28.183,53.85 v1(28.202,53.87) CF1.2@29.483,53.87 ; v1@28.303,37.72 v1(28.303,37.71) CF10.2@29.464,37.71 ; v1(28.47,43.9) CF15.2@29.454,43.9 ; v1(28.54,39.76) C18.1@29.483,39.76 ; v1(29.03,74.88) C21.2@30.152,74.88 30.152,73.238 v1(30.6,72.79) ; C8.1@32.188,94.84 v1(33.67,94.84) ; C7.1@33.183,103.113 v1(33.947,103.876) ; U2.71@33.39,49.14 34.97,49.14 v1(35.29,49.46) ; U2.61@33.39,54.14 34.79,54.14 v1(35.17,54.52) ; v1(34.21,71.14) 35.171,71.14 C17.1@35.291,71.02 35.343,70.968 C27.1@35.343,69.81 ; U2.90@35.69,38.84 v1(35.69,40.8) ; v1(38.69,62.53) U2.37@38.69,63.94 ; CF14.2@38.91,67.277 38.91,68.23 v1(38.92,68.24) ; C25.1@39.458,69.78 C26.1@39.458,71.04 v1(39.458,72.248) ; v1(40.09,17.785) 40.113,17.762 C24.1@40.113,14.855 ; LED1.2@40.563,93.436 40.563,92.157 v1(40.57,92.15) ; v1(41.26,40.56) 41.69,40.13 U2.102@41.69,38.84 ; CF3.2@41.98,35.143 41.98,34.141 v1(41.99,34.131) ; C15.1@44.96,72.36 C16.1@46.421,72.36 ; U2.22@46.19,63.94 46.19,65.06 46.658,65.528 CF12.2@46.658,65.88 v1(46.658,66.67) ; U2.113@47.19,38.84 47.19,37.67 46.65,37.13 46.65,34.38 47.048,33.981 47.71,33.981 CF4.2@47.71,35.093 ; U2.14@50.19,63.94 50.19,65.114 50.618,65.543 CF9.2@50.618,65.94 50.618,66.698 v1(50.62,66.7) ; C13.1@50.599,72.4 51.922,72.4 C14.1@51.932,72.41 ; v1(50.71,114.175) C23.1@52.103,114.175 ; C28.1@53.46,67.467 v1(53.46,68.23) ; CF5.2@53.68,35.121 53.68,32.8 v1(54.55,31.93) ; U2.126@53.69,38.84 v1(53.69,40.66) ; v1(55.62,42.84) 56.31,43.53 56.31,47.62 56.83,48.14 U2.148@58.49,48.14 ; v1(56.15,51.75) 56.15,52.66 56.63,53.14 U2.158@58.49,53.14 ; v1(56.87,41.11) 57.4,41.64 U2.135@58.49,41.64 ; v1(57.34,68.58) 57.76,68.58 57.99,68.35 CF8.2@57.99,67.468 ; U4.1@57.72,104.13 v1(57.72,101.823) C9.1@58.283,101.26 ; C19.2@58.61,35.13 59.232,35.13 v1(59.24,35.121) ; CF7.2@62.23,53.41 63.632,53.41 v1(63.642,53.4) 63.642,53.44 63.622,53.42 v1@63.602,53.42 ; CF6.2@62.25,48.4 v1(63.563,48.4) v1@63.573,48.41 ; CF13.2@62.258,41.85 v1(66.1,41.85) ; C3.1@62.423,8.57 62.423,5.267 63.578,4.112 B3.1@65.93,4.112 B3.4@74.93,4.112 ; R22.1@64.234,114.226 64.234,113.085 64.494,112.825 v1(64.899,112.825) 65.304,112.825 65.514,113.035 R24.1@65.514,114.216 ; C1.1@65.947,101.173 65.947,99.883 v1(65.98,99.85) ; v1(76.75,67.64) R9.1@77.78,67.64 ; B1.1@100.57,2.7 B2.1@111.59,2.7 B2.4@120.59,2.7 ; U3.15@107.855,97.734 v1(108.994,97.735) ; C11.2@107.878,93.578 108.66,93.578 C12.1@109.268,93.578 ; v1(110.236,60.55) CF11.2@111.213,60.55 ; v1(111.301,48.89) 111.301,48.87 111.291,48.86 111.301,48.85 CF2.2@112.673,48.85 ; v1(111.421,53.87) 111.403,53.852 111.403,53.85 111.423,53.87 CF1.2@112.703,53.87 ; v1@111.523,37.72 v1(111.523,37.71) CF10.2@112.684,37.71 ; v1(111.69,43.9) CF15.2@112.673,43.9 ; v1(111.76,39.76) C18.1@112.703,39.76 ; v1(112.25,74.88) C21.2@113.372,74.88 113.372,73.238 v1(113.82,72.79) ; C8.1@115.408,94.84 v1(116.89,94.84) ; C7.1@116.403,103.113 v1(117.167,103.876) ; U2.71@116.61,49.14 118.19,49.14 v1(118.51,49.46) ; U2.61@116.61,54.14 118.01,54.14 v1(118.39,54.52) ; v1(117.43,71.14) 118.391,71.14 C17.1@118.511,71.02 118.563,70.968 C27.1@118.563,69.81 ; U2.90@118.91,38.84 v1(118.91,40.8) ; v1(121.91,62.53) U2.37@121.91,63.94 ; CF14.2@122.13,67.277 122.13,68.23 v1(122.14,68.24) ; C25.1@122.678,69.78 C26.1@122.678,71.04 v1(122.678,72.249) ; v1(123.31,17.785) 123.333,17.762 C24.1@123.333,14.855 ; LED1.2@123.783,93.436 123.783,92.157 v1(123.79,92.15) ; v1(124.48,40.56) 124.91,40.13 U2.102@124.91,38.84 ; CF3.2@125.2,35.143 125.2,34.142 v1(125.21,34.132) ; C15.1@128.18,72.36 C16.1@129.641,72.36 ; U2.22@129.41,63.94 129.41,65.06 129.878,65.528 CF12.2@129.878,65.88 v1(129.878,66.67) ; U2.113@130.41,38.84 130.41,37.67 129.87,37.13 129.87,34.38 130.268,33.982 130.93,33.982 CF4.2@130.93,35.093 ; U2.14@133.41,63.94 133.41,65.114 133.838,65.543 CF9.2@133.838,65.94 133.838,66.699 v1(133.84,66.7) ; C13.1@133.818,72.4 135.141,72.4 C14.1@135.151,72.41 ; v1(133.93,114.175) C23.1@135.323,114.175 ; C28.1@136.68,67.467 v1(136.68,68.23) ; CF5.2@136.9,35.122 136.9,32.8 v1(137.77,31.93) ; U2.126@136.91,38.84 v1(136.91,40.66) ; v1(138.84,42.84) 139.53,43.53 139.53,47.62 140.05,48.14 U2.148@141.71,48.14 ; v1(139.37,51.75) 139.37,52.66 139.85,53.14 U2.158@141.71,53.14 ; v1(140.09,41.11) 140.62,41.64 U2.135@141.71,41.64 ; v1(140.56,68.58) 140.98,68.58 141.21,68.35 CF8.2@141.21,67.469 ; U4.1@140.94,104.13 v1(140.94,101.823) C9.1@141.503,101.26 ; C19.2@141.83,35.13 142.451,35.13 v1(142.46,35.122) ; CF7.2@145.45,53.41 146.851,53.41 v1(146.861,53.4) 146.861,53.44 146.841,53.42 v1@146.821,53.42 ; CF6.2@145.47,48.4 v1(146.783,48.4) v1@146.793,48.41 ; CF13.2@145.478,41.85 v1(149.32,41.85) ; C3.1@145.643,8.57 145.643,5.267 146.798,4.112 B3.1@149.15,4.112 B3.4@158.15,4.112 ; R22.1@147.454,114.226 147.454,113.085 147.714,112.825 v1(148.119,112.825) 148.524,112.825 148.734,113.035 R24.1@148.734,114.216 ; C1.1@149.167,101.173 149.167,99.883 v1(149.2,99.85) ; v1(159.97,67.64) R9.1@161,67.64
  Top Layer w0.3: R33.1@26.063,63.31 26.063,63.913 26.54,64.39 v1(27.02,64.39) ; R33.1@109.283,63.31 109.283,63.913 109.76,64.39 v1(110.24,64.39)
  Top Layer w0.5: v1(64.974,106.825) 65.363,107.214 C2.2@66.88,107.214 ; v1(148.194,106.825) 148.583,107.214 C2.2@150.1,107.214
  Top Layer w0.75: C10.2@53.72,104.08 57.67,104.08 U4.1@57.72,104.13 ; C10.2@136.94,104.08 140.89,104.08 U4.1@140.94,104.13
  other v1: 21.5,2.658 32.82,2.658 104.72,2.658 116.04,2.658 70.29,4.1 153.51,4.1 68.57,9.43 69.46,9.43 70.32,9.426 71.22,9.426 151.79,9.43 152.68,9.43 153.54,9.426 154.44,9.426 19.68,9.94 102.9,9.94 19.68,10.83 102.9,10.83 19.684,11.69 102.904,11.69 22.05,11.86 105.27,11.86 19.69,12.62 102.91,12.62 22.05,12.75 105.27,12.75 22.054,13.61 105.274,13.61 32.49,13.85 115.71,13.85 29.81,13.86 30.7,13.86 31.56,13.856 113.03,13.86 113.92,13.86 114.78,13.856 22.06,14.54 105.28,14.54 52.429,19.425 76.2,19.44 77.09,19.44 135.649,19.425 159.42,19.44 160.31,19.44 52.429,20.325 135.649,20.325 52.428,21.145 135.648,21.145 37.9,21.19 38.79,21.19 39.65,21.186 40.55,21.186 121.12,21.19 122.01,21.19 122.87,21.186 123.77,21.186 52.428,21.955 135.648,21.955 62.296,22.28 145.516,22.28 61.667,22.909 144.887,22.909 39.791,23.25 40.681,23.25 41.541,23.246 42.441,23.246 123.011,23.25 123.901,23.25 124.761,23.246 125.661,23.246 61.061,23.52 144.281,23.52 55.29,27.16 138.51,27.16 54.16,27.28 137.38,27.28 67.69,28.24 150.91,28.24 53.54,28.3 136.76,28.3 67.061,28.869 150.281,28.869 66.455,29.48 149.675,29.48 65.819,30.117 149.039,30.117 78.12,30.85 78.89,30.85 161.34,30.85 162.11,30.85 63.127,33.237 146.347,33.237 62.498,33.867 145.718,33.867 47.7,33.971 130.92,33.972 61.893,34.477 145.113,34.477 57.576,36.32 140.796,36.32 57.576,37.22 140.796,37.22 57.58,38.08 140.8,38.08 67.335,40.61 150.555,40.61 66.729,41.221 149.949,41.221 39.126,41.335 122.346,41.335 39.13,42.195 122.35,42.195 39.13,42.945 122.35,42.945 23.16,43.924 24.06,43.924 24.92,43.92 25.81,43.92 106.38,43.924 107.28,43.924 108.14,43.92 109.03,43.92 36.03,45.78 119.25,45.78 36.03,46.68 119.25,46.68 36.034,47.54 119.254,47.54 35.05,52.524 35.94,52.524 118.27,52.524 119.16,52.524 75.73,54.31 76.59,54.306 77.48,54.306 158.95,54.31 159.81,54.306 160.7,54.306 24.68,62.87 107.9,62.87 23.691,65.413 106.911,65.413 23.062,66.043 106.282,66.043 22.456,66.654 105.676,66.654 21.82,67.29 105.04,67.29 78.98,67.58 162.2,67.58 46.94,67.904 47.8,67.9 48.69,67.9 130.16,67.904 131.02,67.9 131.91,67.9 44.68,70.928 127.9,70.928 45.38,70.938 128.6,70.938 46.03,70.964 129.25,70.964 45.67,72.35 128.89,72.35 51.3,72.41 134.52,72.41 35.19,72.96 118.41,72.96 35.19,73.85 118.41,73.85 35.194,74.71 118.414,74.71 35.194,75.61 118.414,75.61 6.18,76.34 89.4,76.34 6.18,77.23 89.4,77.23 41.961,77.643 125.181,77.643 6.184,78.09 89.404,78.09 41.325,78.28 124.545,78.28 40.719,78.891 123.939,78.891 6.184,78.99 89.404,78.99 40.09,79.52 123.31,79.52 35.23,80.3 118.45,80.3 60.05,80.96 143.27,80.96 31.54,81.2 35.23,81.2 114.76,81.2 118.45,81.2 31.544,82.06 35.234,82.06 114.764,82.06 118.454,82.06 6.16,82.16 89.38,82.16 31.544,82.96 35.234,82.95 114.764,82.96 118.454,82.95 6.16,83.05 89.38,83.05 6.164,83.91 89.384,83.91 52.84,83.99 136.06,83.99 38.36,84.445 121.58,84.445 52.235,84.601 135.455,84.601 26.14,84.68 27.04,84.68 27.9,84.676 109.36,84.68 110.26,84.68 111.12,84.676 6.164,84.81 89.384,84.81 33.13,84.884 35.84,84.895 116.35,84.884 119.06,84.895 51.605,85.23 134.825,85.23 38.36,85.38 121.58,85.38 33.13,85.819 35.84,85.83 116.35,85.819 119.06,85.83 65.33,86.58 148.55,86.58 65.966,87.216 149.186,87.216 46.52,87.32 129.74,87.32 66.577,87.822 149.797,87.822 45.891,87.949 129.111,87.949 30.75,88.17 113.97,88.17 33.29,88.2 116.51,88.2 28.1,88.21 111.32,88.21 67.207,88.451 150.427,88.451 45.285,88.56 128.505,88.56 50.493,88.633 133.713,88.633 6.22,89.21 44.649,89.196 89.44,89.21 127.869,89.197 49.857,89.27 133.077,89.27 49.251,89.881 132.471,89.881 6.22,90.1 89.44,90.1 48.622,90.51 131.842,90.51 30.57,90.525 113.79,90.525 33.24,90.79 116.46,90.79 28.24,90.84 111.46,90.84 27.48,90.87 110.7,90.87 6.224,90.96 89.444,90.96 30.57,91.46 113.79,91.46 6.224,91.86 89.444,91.86 57.524,92.335 140.744,92.335 53.5,92.39 136.72,92.39 32.49,92.6 115.71,92.6 53.5,93.29 136.72,93.29 25.44,93.55 108.66,93.55 53.504,94.15 66.7,94.16 136.724,94.15 149.92,94.16 58.35,94.53 141.57,94.53 53.504,95.04 66.67,95.055 136.724,95.04 149.89,95.055 62.32,95.06 145.54,95.06 58.35,95.43 141.57,95.43 66.67,95.945 149.89,95.945 62.32,95.95 145.54,95.95 58.354,96.29 141.574,96.29 39.09,96.427 122.31,96.427 62.324,96.81 145.544,96.81 35.58,96.83 118.8,96.83 58.354,97.18 141.574,97.18 28.736,97.22 111.956,97.22 39.09,97.317 122.31,97.317 66.664,97.495 149.884,97.495 62.324,97.71 145.544,97.71 35.58,97.73 118.8,97.73 28.736,98.11 111.956,98.11 39.094,98.177 122.314,98.177 66.664,98.395 149.884,98.395 35.584,98.59 118.804,98.59 28.74,98.97 111.96,98.97 39.094,99.077 122.314,99.077 35.584,99.48 118.804,99.48 28.74,99.87 111.96,99.87 43.84,100.254 44.7,100.25 45.59,100.25 127.06,100.254 127.92,100.25 128.81,100.25 16.546,102.25 99.766,102.25 22.036,102.904 105.256,102.904 49.65,102.99 132.87,102.99 16.546,103.14 99.766,103.14 22.036,103.804 105.256,103.804 49.65,103.88 132.87,103.88 16.55,104 99.77,104 22.04,104.664 105.26,104.664 49.654,104.74 132.874,104.74 22.03,105.505 105.25,105.505 49.654,105.64 132.874,105.64 61.67,106.75 62.56,106.75 144.89,106.75 145.78,106.75 50.66,109.075 133.88,109.075 55.34,109.62 138.56,109.62 55.34,110.52 138.56,110.52 55.344,111.38 138.564,111.38 55.344,112.27 138.564,112.27 55.186,115.325 138.406,115.325 48.974,115.625 132.194,115.625 55.186,116.225 138.406,116.225 55.19,117.085 138.41,117.085 55.19,117.975 138.41,117.975
LED2: LED2.2 P1.1 U2.5 | length 133.7
  Top Layer w0.254: LED2.2@43.907,93.424 43.907,91.813 v1(55.92,79.8) ; U2.5@54.69,63.94 54.69,74.19 76.761,96.261 P1.1@80.431,96.261 ; LED2.2@127.127,93.424 127.127,91.813 v1(139.14,79.8) ; U2.5@137.91,63.94 137.91,74.19 159.981,96.261 P1.1@163.651,96.261
  Bottom Layer w0.254: v1(55.92,79.8) 58.11,77.61 v1(58.11,77.6) ; v1(139.14,79.8) 141.33,77.61 v1(141.33,77.6)
LED3: LED3.2 P1.2 U2.4 | length 135.7
  Top Layer w0.254: LED3.2@45.76,93.406 45.76,92.2 v1(57.72,80.24) ; U2.4@55.19,63.94 55.19,73.79 v1(59.68,78.28) 76.37,94.97 81.68,94.97 P1.2@82.971,96.261 ; LED3.2@128.98,93.406 128.98,92.2 v1(140.94,80.24) ; U2.4@138.41,63.94 138.41,73.79 v1(142.9,78.28) 159.59,94.97 164.9,94.97 P1.2@166.191,96.261
  Bottom Layer w0.254: v1(57.72,80.24) v1(59.68,78.28) ; v1(140.94,80.24) v1(142.9,78.28)
NetC4_1: C4.1 U3.1 | length 4.8
  Top Layer w0.254: U3.1@31.035,97.084 31.691,97.084 32.711,96.064 C4.1@33.017,96.064 ; U3.1@114.255,97.084 114.911,97.084 115.931,96.064 C4.1@116.237,96.064
NetC4_2: C4.2 U3.3 | length 4.7
  Top Layer w0.254: U3.3@31.035,98.384 32.094,98.384 C4.2@33.017,97.461 ; U3.3@114.255,98.384 115.314,98.384 C4.2@116.237,97.461
NetC5_1: C5.1 U3.4 | length 4.1
  Top Layer w0.254: U3.4@31.035,99.034 32.905,99.034 C5.1@33.017,98.922 ; U3.4@114.255,99.034 116.125,99.034 C5.1@116.237,98.922
NetC5_2: C5.2 U3.5 | length 4.5
  Top Layer w0.254: U3.5@31.035,99.684 32.382,99.684 C5.2@33.017,100.319 ; U3.5@114.255,99.684 115.602,99.684 C5.2@116.237,100.319
NetC7_2: C7.2 U3.6 | length 5.1
  Top Layer w0.254: U3.6@31.035,100.334 31.675,100.334 32.953,101.612 C7.2@32.953,101.716 ; U3.6@114.255,100.334 114.895,100.334 116.173,101.612 C7.2@116.173,101.716
NetC8_2: C8.2 U3.2 | length 8.2
  Top Layer w0.254: C8.2@30.814,94.843 30.814,95.635 29.974,96.475 29.974,97.404 30.304,97.734 U3.2@31.035,97.734 ; C8.2@114.034,94.843 114.034,95.635 113.194,96.475 113.194,97.404 113.524,97.734 U3.2@114.255,97.734
NetC11_1: C11.1 C12.2 R3.1 U3.16 | length 9.6
  Top Layer w0.254: U3.16@24.635,97.084 24.635,94.998 C11.1@24.658,94.975 24.66,94.977 R3.1@27.36,94.977 ; U3.16@107.855,97.084 107.855,94.998 C11.1@107.878,94.975 107.88,94.977 R3.1@110.58,94.977
NetC15_2: C15.2 R14.2 U2.30 Y2.1 | length 28.5
  Top Layer w0.254: U2.30@42.19,63.94 42.19,65.52 43.913,67.243 R14.2@43.913,68.44 43.913,69.897 43.563,70.247 C15.2@43.563,72.36 43.563,75.413 44.36,76.21 Y2.1@45.17,76.21 ; U2.30@125.41,63.94 125.41,65.52 127.133,67.243 R14.2@127.133,68.44 127.133,69.897 126.783,70.247 C15.2@126.783,72.36 126.783,75.413 127.58,76.21 Y2.1@128.39,76.21
NetC16_2: C16.2 R14.1 U2.29 Y2.2 | length 32.7
  Top Layer w0.254: U2.29@42.69,63.94 42.69,65.17 45.31,67.79 R14.1@45.31,68.44 47.818,70.948 C16.2@47.818,72.36 47.818,75.358 48.67,76.21 Y2.2@50.25,76.21 ; U2.29@125.91,63.94 125.91,65.17 128.53,67.79 R14.1@128.53,68.44 131.038,70.948 C16.2@131.038,72.36 131.038,75.358 131.89,76.21 Y2.2@133.47,76.21
NetC24_2: C24.2 J2.0 R31.2 | length 36.1
  Top Layer w0.254: R31.2@41.52,16.295 41.52,12.615 J2.0@43.06,11.075 J2.0@55.252,11.075 ; R31.2@124.74,16.295 124.74,12.615 J2.0@126.28,11.075 J2.0@138.472,11.075
NetC29_1: C29.1 PJ1.1 | length 4.4
  Top Layer w0.254: PJ1.1@34.05,21.54 34.05,19.417 C29.1@34.117,19.35 ; PJ1.1@117.27,21.54 117.27,19.417 C29.1@117.337,19.35
NetC30_1: C30.1 PJ2.1 | length 4.6
  Top Layer w0.254: C30.1@31.18,19.36 31.18,20.34 31.52,20.68 PJ2.1@31.52,21.54 ; C30.1@114.4,19.36 114.4,20.34 114.74,20.68 PJ2.1@114.74,21.54
NetC31_1: C31.1 R15.2 R16.1 RFJ2.5 | length 46.5
  Top Layer w0.254: RFJ2.5@35.48,14.15 35.48,20.813 cw(c36.777,20.813) 35.859,21.729 36.13,22 cw(c37.289,20.841) 37.289,22.48 45.875,22.48 ccw(c45.875,23.965) 46.924,22.914 ; 46.925,22.915 47.165,23.155 ccw(c46.072,24.248) 47.618,24.248 R16.1@47.618,25.075 cw(c49.718,25.075) 48.233,26.56 R15.2@48.333,26.66 ; RFJ2.5@118.7,14.15 118.7,20.813 cw(c119.997,20.813) 119.079,21.729 ; 119.08,21.73 119.35,22 cw(c120.509,20.841) 120.509,22.48 129.095,22.48 ccw(c129.095,23.965) 130.144,22.914 130.385,23.155 ccw(c129.292,24.248) 130.838,24.248 R16.1@130.838,25.075 cw(c132.938,25.075) 131.453,26.56 R15.2@131.552,26.66
NetJ1_1: J1.1 R29.2 | length 15.4
  Top Layer w0.254: R29.2@19.081,110.805 19.081,115.046 19.91,115.875 J1.1@22.176,115.875 ; R29.2@102.301,110.805 102.301,115.046 103.13,115.875 J1.1@105.396,115.875
NetJ1_4: J1.4 R29.1 | length 42
  Top Layer w0.254: R29.1@20.478,110.805 21.67,110.805 23.62,112.755 23.62,116.895 24.27,117.545 v1(24.74,117.545) ; R29.1@103.698,110.805 104.89,110.805 106.84,112.755 106.84,116.895 107.49,117.545 v1(107.96,117.545)
  Bottom Layer w0.254: v1(24.74,117.545) 24.959,117.326 28.789,117.326 29.05,117.065 29.05,113.775 29.33,113.495 30.16,113.495 30.481,113.816 J1.4@30.481,115.875 ; v1(107.96,117.545) 108.179,117.326 112.009,117.326 112.27,117.065 112.27,113.775 112.55,113.495 113.38,113.495 113.701,113.816 J1.4@113.701,115.875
